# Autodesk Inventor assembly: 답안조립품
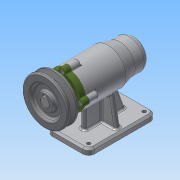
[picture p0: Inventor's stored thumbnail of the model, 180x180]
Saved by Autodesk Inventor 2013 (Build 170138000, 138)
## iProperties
Created: 2019-07
Part Number: 답안조립품
Document SubType Name: Assembly
Designer: Administrator
Author: Administrator
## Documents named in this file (12)
- C:\Users\Administrator\Desktop\490704V1066\답안조립품.iam
- C:\Users\Administrator\Desktop\490704V1066\부품1.ipt
- C:\Users\Administrator\Desktop\490704V1066\V벨트풀리.ipt
- C:\Users\Administrator\Desktop\490704V1066\멈춤나사 M3.ipt
- C:\Users\Administrator\Desktop\490704V1066\베어링 6004.ipt
- C:\Users\Administrator\Desktop\490704V1066\베어링 51202.ipt
- C:\Users\Administrator\Desktop\490704V1066\볼트 M4.ipt
- C:\Users\Administrator\Desktop\490704V1066\어댑터슬리브.ipt
- C:\Users\Administrator\Desktop\490704V1066\오일 실.ipt
- C:\Users\Administrator\Desktop\490704V1066\축.ipt
- C:\Users\Administrator\Desktop\490704V1066\커버.ipt
- C:\Users\Administrator\Desktop\490704V1066\키 5 x 5 x 16.ipt
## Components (1 placed, 1 different names)
1. V벨트풀리:1
